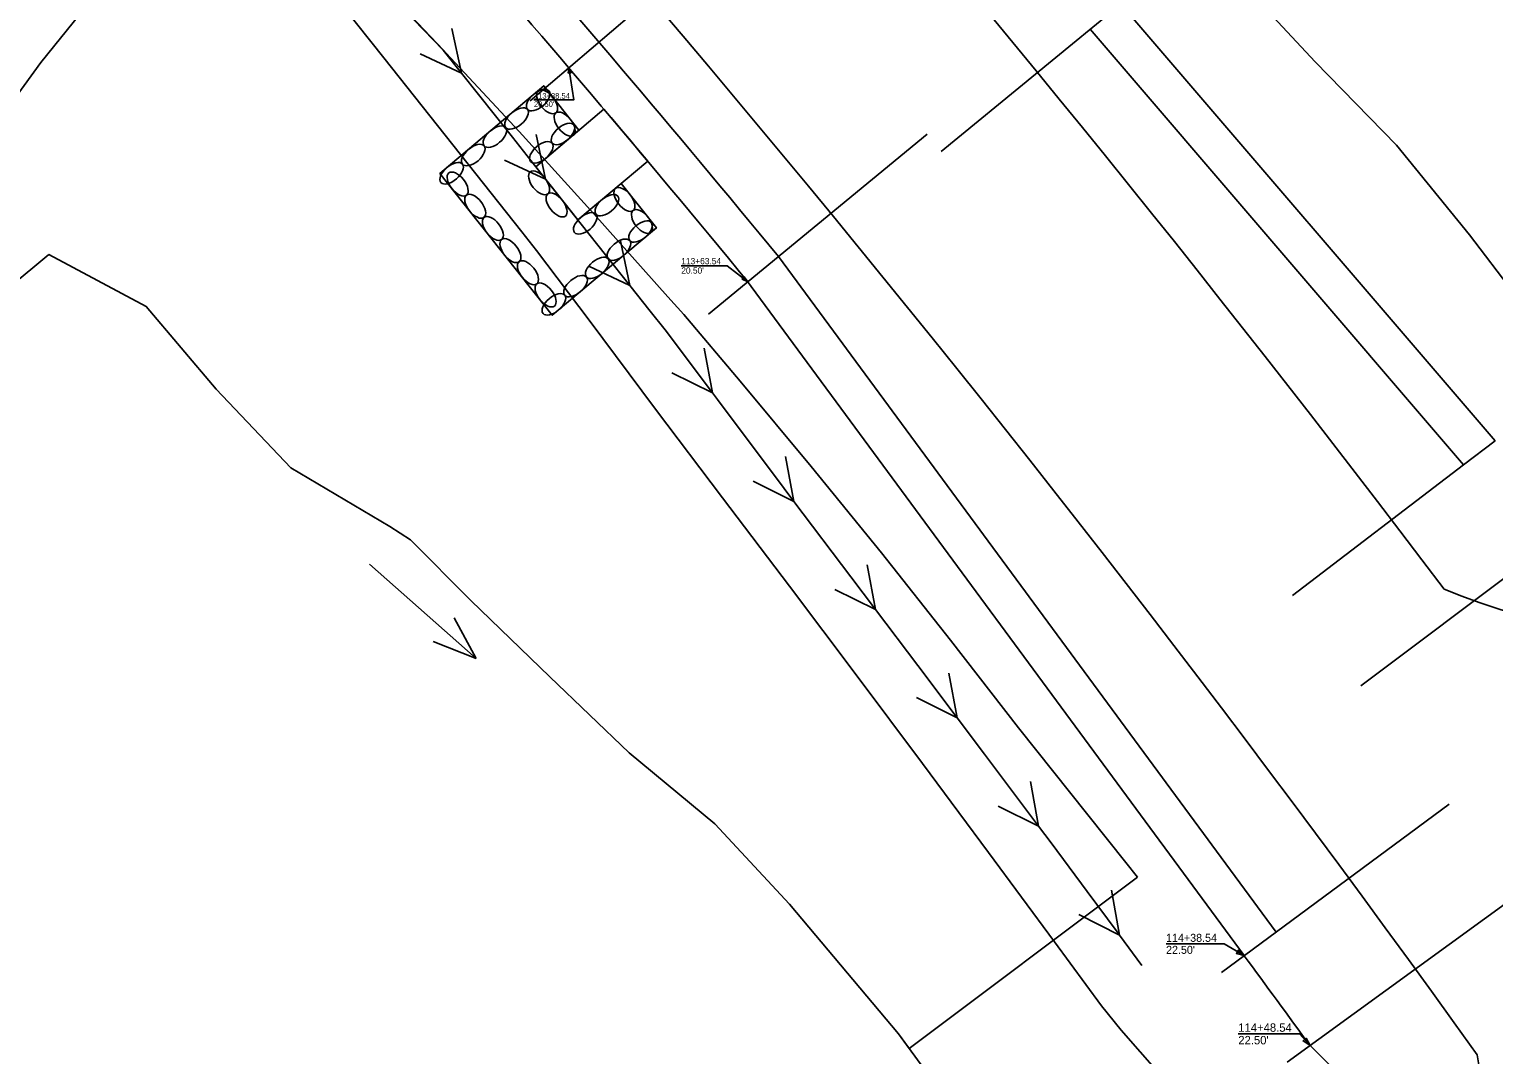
# Model space of a CAD drawing. Extents: x 1006695 to 1009377, y 1883329 to 1886115.
# Drawn here: x 1007928.2 to 1008057.5, y 1884510 to 1884600.5 of the extents above; entities that cross this region are included whole.
import ezdxf

# ---------------------------------------------------------------- set-up
doc = ezdxf.new("R2010")
doc.units = 0
for name, color, linetype in [('B_Hatch', 7, 'Continuous'), ('R_Drainage Concrete Lining', 7, 'Continuous'), ('R_I-30 Information', 7, 'Continuous'), ('R_No Plot', 7, 'Continuous'), ('R_Prop Const Limits Cut', 7, 'Continuous'), ('R_Prop EOL', 7, 'Continuous'), ('R_Prop EOS', 7, 'Continuous'), ('R_Prop Guardrail', 7, 'Continuous'), ('R_Water Annot', 7, 'Continuous')]:
    doc.layers.add(name, color=color, linetype=linetype)

msp = doc.modelspace()

# ---------------------------------------------------------------- linework, layer by layer
at = {"layer": 'B_Hatch'}
for p in [(1008005.91, 1884510.5), (1008026.06, 1884525.62)]:
    msp.add_line(p, (1008026.06, 1884525.62), dxfattribs=at)
for points in [[(1007965.03, 1884598.37), (1007964.77, 1884598.65), (1007959.59, 1884604.1), (1007958.27, 1884605.48)], [(1007965.03, 1884598.37), (1007964.77, 1884598.65), (1007959.59, 1884604.1), (1007958.27, 1884605.48)], [(1008026.06, 1884525.62), (1008025.04, 1884526.91), (1008021.67, 1884531.12), (1008015.56, 1884538.8), (1008009.55, 1884546.56), (1008003.46, 1884554.27), (1007997.26, 1884561.87), (1007990.99, 1884569.43), (1007986, 1884575.29), (1007984.59, 1884576.87), (1007978.05, 1884584.19), (1007971.45, 1884591.46), (1007965.03, 1884598.37)], [(1008026.06, 1884525.62), (1008025.04, 1884526.91), (1008021.67, 1884531.12), (1008015.56, 1884538.8), (1008009.55, 1884546.56), (1008003.46, 1884554.27), (1007997.26, 1884561.87), (1007990.99, 1884569.43), (1007986, 1884575.29), (1007984.59, 1884576.87), (1007978.05, 1884584.19), (1007971.45, 1884591.46), (1007965.03, 1884598.37)], [(1007897.65, 1884553.78), (1007929.93, 1884580.6)], [(1007929.93, 1884580.6), (1007938.53, 1884576.02), (1007944.7, 1884568.71), (1007951.3, 1884561.77), (1007960.04, 1884556.58), (1007961.86, 1884555.41), (1007967.2, 1884550.04), (1007974.17, 1884543.33), (1007981.18, 1884536.62), (1007988.75, 1884530.33), (1007995.34, 1884523.25), (1008001.56, 1884515.87), (1008004.96, 1884511.8), (1008005.91, 1884510.5)]]:
    msp.add_lwpolyline(points, dxfattribs=at)
at = {"layer": 'R_Drainage Concrete Lining'}
for p, q in [((1007972.92, 1884588.35), (1007978.94, 1884593.44)), ((1007978.94, 1884593.44), (1007982.82, 1884588.84)), ((1007976.65, 1884583.65), (1007982.82, 1884588.84))]:
    msp.add_line(p, q, dxfattribs=at)
msp.add_lwpolyline([(1007972.92, 1884588.35), (1007973.8, 1884587.24), (1007976.65, 1884583.65)], dxfattribs=at)
for centre, major_axis in [((1007973.14, 1884594.23), (-0.954, -0.807)), ((1007973.93, 1884594.08), (-0.777, 0.979)), ((1007971.23, 1884592.61), (-0.954, -0.807)), ((1007975.48, 1884592.12), (-0.777, 0.979)), ((1007969.32, 1884591), (-0.954, -0.807)), ((1007975.33, 1884591.24), (0.954, 0.807)), ((1007967.41, 1884589.38), (-0.954, -0.807)), ((1007973.42, 1884589.62), (0.954, 0.807)), ((1007965.5, 1884587.77), (-0.954, -0.807)), ((1007966.03, 1884586.82), (0.777, -0.979)), ((1007973.22, 1884586.93), (-0.777, 0.979)), ((1007980.76, 1884585.46), (-0.777, 0.979)), ((1007967.58, 1884584.86), (0.777, -0.979)), ((1007974.77, 1884584.97), (-0.777, 0.979)), ((1007979.21, 1884584.96), (-0.958, -0.803)), ((1007969.14, 1884582.9), (0.777, -0.979)), ((1007977.3, 1884583.35), (-0.958, -0.803)), ((1007982.31, 1884583.51), (-0.777, 0.979)), ((1007982.19, 1884582.63), (0.958, 0.803)), ((1007970.69, 1884580.94), (0.777, -0.979)), ((1007980.27, 1884581.02), (0.958, 0.803)), ((1007972.24, 1884578.99), (0.777, -0.979)), ((1007978.36, 1884579.42), (0.958, 0.803)), ((1007976.44, 1884577.81), (0.958, 0.803)), ((1007973.8, 1884577.03), (0.777, -0.979)), ((1007974.53, 1884576.2), (0.958, 0.803))]:
    msp.add_ellipse(centre, major_axis=major_axis, ratio=0.52103, dxfattribs=at)
at = {"layer": 'R_I-30 Information'}
msp.add_lwpolyline([(1007979.45, 1884680.26), (1007976.51, 1884676.2), (1007973.9, 1884671.84), (1007971.94, 1884666.93), (1007969.95, 1884662.05), (1007967.91, 1884657.21), (1007965.2, 1884652.94), (1007962.68, 1884648.97), (1007958.28, 1884646.15), (1007956.17, 1884641.38), (1007954.71, 1884635.67), (1007951.48, 1884631.85), (1007950.13, 1884626.42), (1007946.46, 1884622.97), (1007944.42, 1884618.13), (1007941.26, 1884614.26), (1007939.14, 1884609.48), (1007935.91, 1884605.66), (1007932.68, 1884601.85), (1007929.21, 1884597.56), (1007926.27, 1884593.49)], dxfattribs=at)
at = {"layer": 'R_No Plot'}
for p, q in [((1007972.42, 1884594.17), (1007991.46, 1884610.38)), ((1008028.07, 1884605.55), (1008008.74, 1884589.7)), ((1007966.36, 1884596.62), (1007965.53, 1884600.56)), ((1007966.36, 1884596.62), (1007962.73, 1884598.31)), ((1007972.77, 1884594.24), (1007975.8, 1884594.24)), ((1007973.8, 1884587.24), (1007972.97, 1884591.18)), ((1007988.19, 1884575.33), (1008007.5, 1884591.21)), ((1007973.8, 1884587.24), (1007970.17, 1884588.93)), ((1007981.24, 1884577.86), (1007980.4, 1884581.8)), ((1007981.24, 1884577.86), (1007977.61, 1884579.56)), ((1007985.78, 1884579.6), (1007989.27, 1884579.6)), ((1007988.53, 1884568.38), (1007987.8, 1884572.33)), ((1007988.53, 1884568.38), (1007984.95, 1884570.16)), ((1007995.71, 1884558.8), (1007994.99, 1884562.76)), ((1007995.71, 1884558.8), (1007992.13, 1884560.59)), ((1008063.78, 1884556.05), (1008045.8, 1884542.52)), ((1008002.94, 1884549.25), (1008002.19, 1884553.21)), ((1008002.94, 1884549.25), (1007999.35, 1884551.03)), ((1008010.15, 1884539.7), (1008009.42, 1884543.65)), ((1008010.15, 1884539.7), (1008006.56, 1884541.48)), ((1008017.33, 1884530.12), (1008016.61, 1884534.08)), ((1008017.33, 1884530.12), (1008013.75, 1884531.91)), ((1008033.48, 1884517.21), (1008053.6, 1884532.06)), ((1008024.48, 1884520.52), (1008023.77, 1884524.48)), ((1008039.29, 1884509.29), (1008059.51, 1884523.99)), ((1008024.48, 1884520.52), (1008020.9, 1884522.32)), ((1008028.59, 1884519.74), (1008033.03, 1884519.74)), ((1008034.97, 1884511.8), (1008039.63, 1884511.8))]:
    msp.add_line(p, q, dxfattribs=at)
for points in [[(1007940.14, 1884622.18), (1007941.36, 1884621.16), (1007942.82, 1884619.64), (1007946.61, 1884612.71), (1007946.87, 1884612.44), (1007948.2, 1884611.06), (1007953.41, 1884605.64), (1007959.51, 1884597.95), (1007965.6, 1884590.27), (1007971.69, 1884582.59), (1007973, 1884580.94), (1007977.63, 1884574.79), (1007983.51, 1884566.94), (1007989.42, 1884559.13), (1007995.33, 1884551.32), (1008001.21, 1884543.5), (1008007.08, 1884535.66), (1008010.29, 1884531.35), (1008012.92, 1884527.8), (1008018.74, 1884519.93), (1008022.88, 1884514.28), (1008024.63, 1884512.11), (1008031.12, 1884504.72), (1008037.6, 1884497.3)], [(1007959.55, 1884604.06), (1007964.76, 1884598.64), (1007966.36, 1884596.62), (1007970.86, 1884590.95), (1007973.8, 1884587.24), (1007976.95, 1884583.27), (1007981.24, 1884577.86), (1007983.04, 1884575.59), (1007984.35, 1884573.94), (1007988.53, 1884568.38), (1007988.98, 1884567.79), (1007994.86, 1884559.94), (1007995.72, 1884558.8), (1008000.76, 1884552.13), (1008002.94, 1884549.25), (1008006.67, 1884544.32), (1008010.15, 1884539.7), (1008012.56, 1884536.5), (1008017.33, 1884530.12), (1008018.43, 1884528.66), (1008021.63, 1884524.35), (1008024.27, 1884520.8), (1008024.48, 1884520.52), (1008026.46, 1884517.83)], [(1007975.85, 1884597.09), (1007976.28, 1884594.24), (1007975.8, 1884594.24)], [(1007991.66, 1884578.19), (1007989.83, 1884579.6), (1007989.27, 1884579.6)], [(1008057.65, 1884564.14), (1008054.86, 1884562.02), (1008039.76, 1884550.49)], [(1008035.49, 1884518.7), (1008033.73, 1884519.74), (1008033.03, 1884519.74)], [(1008041.31, 1884510.76), (1008040.38, 1884511.8), (1008039.63, 1884511.8)]]:
    msp.add_lwpolyline(points, dxfattribs=at)
for points in [[(1007975.85, 1884597.09), (1007976.04, 1884596.64), (1007975.8, 1884596.61)], [(1007976.74, 1884591.58), (1007973.63, 1884595.5), (1007964.47, 1884587.74), (1007974.39, 1884575.23), (1007983.59, 1884582.95), (1007980.48, 1884586.87), (1007976.65, 1884583.65), (1007972.92, 1884588.35)], [(1007991.66, 1884578.19), (1007991.16, 1884578.41), (1007991.32, 1884578.62)], [(1008035.49, 1884518.7), (1008034.81, 1884518.9), (1008034.99, 1884519.19)], [(1008041.31, 1884510.76), (1008040.69, 1884511.17), (1008040.96, 1884511.41)]]:
    msp.add_lwpolyline(points, close=True, dxfattribs=at)
at = {"layer": 'R_Prop Const Limits Cut'}
for points in [[(1008028.17, 1884612.88), (1008029.6, 1884611.22), (1008034.78, 1884605.1), (1008041.75, 1884597.61), (1008048.93, 1884590.26), (1008055.4, 1884582.35), (1008066.95, 1884567.16)], [(1007929.93, 1884580.6), (1007897.65, 1884553.78)], [(1007929.93, 1884580.6), (1007938.53, 1884576.02), (1007944.7, 1884568.71), (1007951.3, 1884561.77), (1007960.04, 1884556.58), (1007961.86, 1884555.41), (1007967.2, 1884550.04), (1007974.17, 1884543.33), (1007981.18, 1884536.62), (1007988.75, 1884530.33), (1007995.34, 1884523.25), (1008001.56, 1884515.87), (1008004.96, 1884511.8), (1008007.53, 1884508.3), (1008013.13, 1884503.63)]]:
    msp.add_lwpolyline(points, dxfattribs=at)
at = {"layer": 'R_Prop EOL'}
for centre, radius, start, end in [((1006901.08, 1883681.49), 1443.39, 37.04506, 53.47197), ((1006901.08, 1883681.49), 1421.39, 35.65164, 53.47197), ((1008082.8, 1884625.35), 80, 248.2408, 322.0074), ((1007957.43, 1884493.52), 100, 305.6982, 9.4588)]:
    msp.add_arc(centre, radius, start, end, dxfattribs=at)
at = {"layer": 'R_Prop EOS'}
for p, q in [((1008024.59, 1884602.7), (1008057.65, 1884564.14)), ((1007991.55, 1884578.34), (1008035.49, 1884518.7)), ((1008041.31, 1884510.76), (1008053.29, 1884498.76))]:
    msp.add_line(p, q, dxfattribs=at)
for radius, start, end in [(1411.89, 39.42775, 41.17775), (1409.89, 36.02775, 36.42775)]:
    msp.add_arc((1006901.08, 1883681.49), radius, start, end, dxfattribs=at)
at = {"layer": 'R_Prop Guardrail'}
for p, q in [((1008021.88, 1884600.48), (1008054.86, 1884562.02)), ((1007994.37, 1884580.41), (1008038.31, 1884520.77))]:
    msp.add_line(p, q, dxfattribs=at)
msp.add_arc((1006901.08, 1883681.49), 1415.39, 39.42775, 41.17775, dxfattribs=at)
at = {"layer": 'R_Water Annot'}
for p, q in [((1007958.25, 1884553.25), (1007967.67, 1884544.94)), ((1007967.67, 1884544.94), (1007965.71, 1884548.53)), ((1007967.67, 1884544.94), (1007963.86, 1884546.44))]:
    msp.add_line(p, q, dxfattribs=at)

# ---------------------------------------------------------------- texts
at = {"layer": 'R_No Plot'}
for s, height, p in [('113+38.54', 0.483, (1007972.77, 1884594.36)), ("20.50'", 0.483, (1007972.77, 1884593.63)), ('113+63.54', 0.552, (1007985.78, 1884579.74)), ("20.50'", 0.552, (1007985.78, 1884578.91)), ('114+38.54', 0.707, (1008028.59, 1884519.92)), ("22.50'", 0.707, (1008028.59, 1884518.86)), ('114+48.54', 0.743, (1008034.97, 1884511.98)), ("22.50'", 0.743, (1008034.97, 1884510.87))]:
    msp.add_text(s, height=height, dxfattribs=at).set_placement(p)

doc.saveas('drawing.dxf')
